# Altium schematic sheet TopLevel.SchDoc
size A4
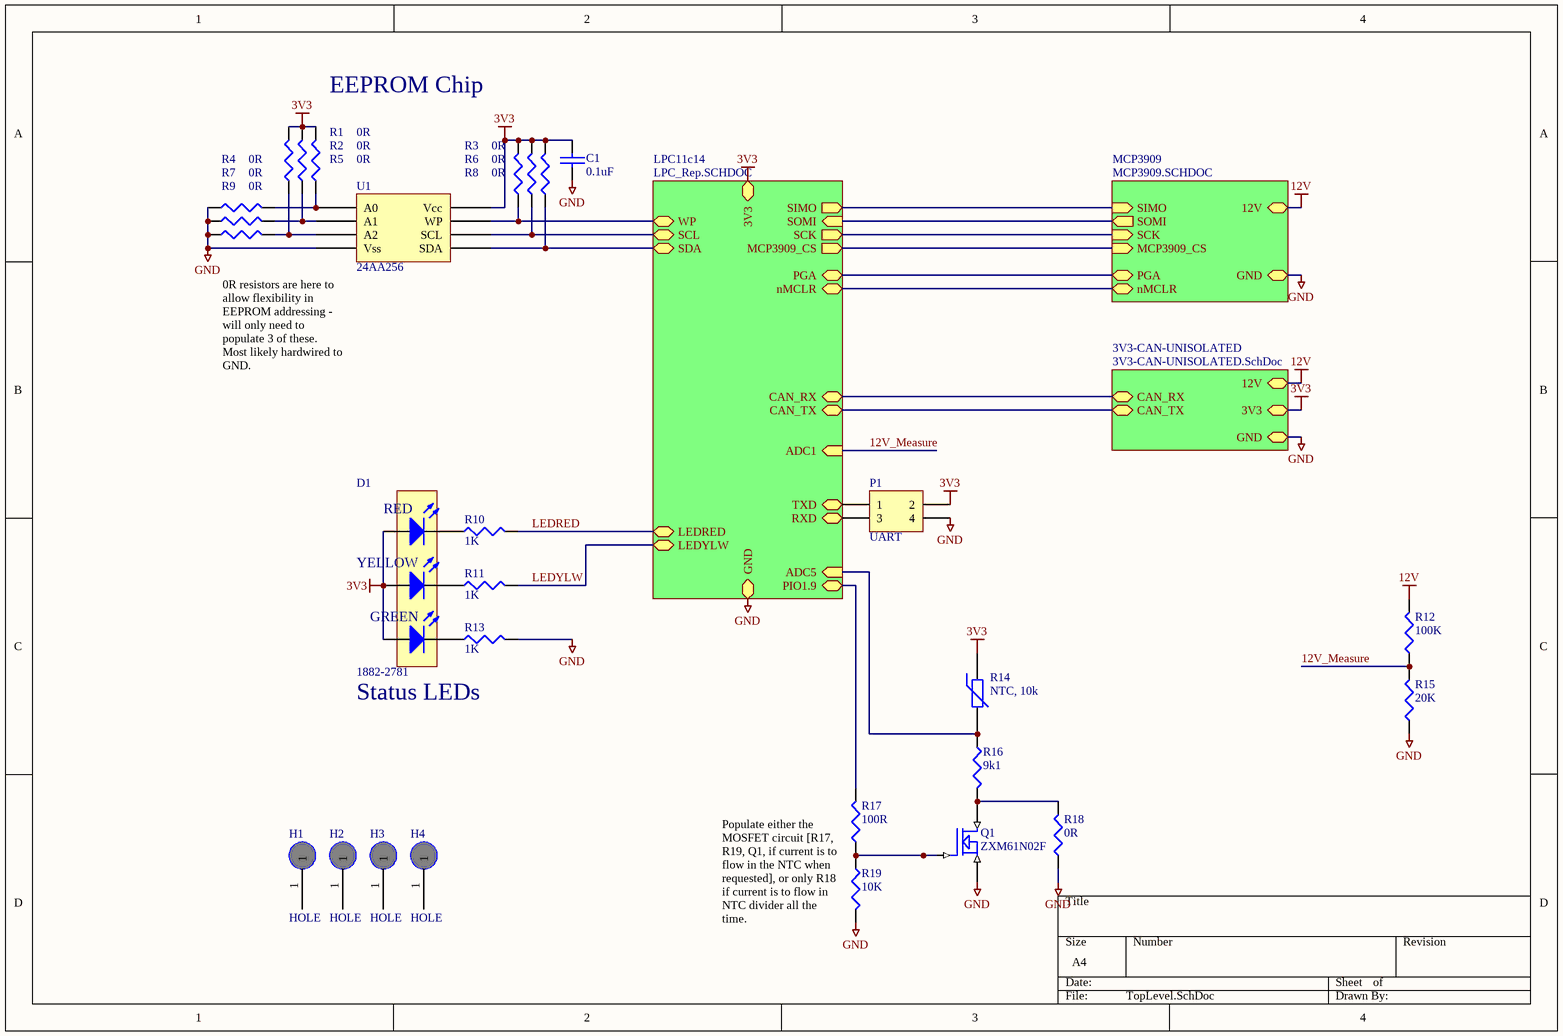
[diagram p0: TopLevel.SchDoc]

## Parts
C1  0.1uF  [0805]
D1  1882-2781  [LED_TRILEVEL]
H1  HOLE  [M2.5]
H2  HOLE  [M2.5]
H3  HOLE  [M2.5]
H4  HOLE  [M2.5]
P1  UART  [HDR2X2]
Q1  ZXM61N02F  [SOT23-3]
R1  0R  [0603]
R2  0R  [0603]
R3  0R  [0603]
R4  0R  [0603]
R5  0R  [0603]
R6  0R  [0603]
R7  0R  [0603]
R8  0R  [0603]
R9  0R  [0603]
R10  1K  [0603]
R11  1K  [0603]
R12  100K  [1206]
R13  1K  [0603]
R14  NTC, 10k  [NTC_EPCOS]
R15  20K  [1206]
R16  9k1  [0603]
R17  100R  [0603]
R18  0R  [0603]
R19  10K  [0603]
U1  24AA256  [DIP8]

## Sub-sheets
3V3-CAN-UNISOLATED = 3V3-CAN-UNISOLATED.SchDoc: CAN_RX, CAN_TX, GND, 12V, 3V3
LPC11c14 = LPC_Rep.SCHDOC: SIMO (out), SOMI (in), SCK (out), MCP3909_CS (out), PGA, nMCLR, CAN_RX, CAN_TX, 3V3, GND, SCL, SDA, WP, LEDRED, LEDYLW, ADC5 (in), PIO1.9, ADC1 (in), TXD, RXD
MCP3909 = MCP3909.SCHDOC: SIMO (in), SOMI (out), SCK (in), MCP3909_CS (in), PGA, nMCLR, 12V, GND

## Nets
3V3: C1.1 D1.4(A) D1.5(A) D1.6(A) P1.2 R1.2 R2.2 R3.2 R5.2 R6.2 R8.2 R14.1 U1.8(Vcc) ; sheet LPC11c14/3V3, sheet 3V3-CAN-UNISOLATED/3V3
12V: R12.2 ; sheet MCP3909/12V, sheet 3V3-CAN-UNISOLATED/12V
GND: C1.2 P1.4 Q1.2(S) R4.1 R7.1 R9.1 R13.2 R15.1 R18.1 R19.2 U1.4(Vss) ; sheet LPC11c14/GND, sheet MCP3909/GND, sheet 3V3-CAN-UNISOLATED/GND
12V_Measure: R12.1 R15.2 ; sheet LPC11c14/ADC1
LEDRED: R10.2 ; sheet LPC11c14/LEDRED
LEDYLW: R11.2 ; sheet LPC11c14/LEDYLW
NetD1_1: D1.1(K) R13.1
NetD1_2: D1.2(K) R11.1
NetD1_3: D1.3(K) R10.1
NetP1_1: P1.1 ; sheet LPC11c14/TXD
NetP1_3: P1.3 ; sheet LPC11c14/RXD
NetQ1_1: Q1.1(G) R17.1 R19.1
NetQ1_3: Q1.3(D) R16.2 R18.2
NetR1_1: R1.1 R4.2 U1.1(A0)
NetR2_1: R2.1 R7.2 U1.2(A1)
NetR3_1: R3.1 U1.5(SDA) ; sheet LPC11c14/SDA
NetR5_1: R5.1 R9.2 U1.3(A2)
NetR6_1: R6.1 U1.6(SCL) ; sheet LPC11c14/SCL
NetR8_1: R8.1 U1.7(WP) ; sheet LPC11c14/WP
NetR14_2: R14.2 R16.1 ; sheet LPC11c14/ADC5
NetR17_2: R17.2 ; sheet LPC11c14/PIO1.9
(unnamed): sheet LPC11c14/SIMO, sheet MCP3909/SIMO
(unnamed): sheet LPC11c14/SOMI, sheet MCP3909/SOMI  [a separate net that carries the same name]
(unnamed): sheet LPC11c14/SCK, sheet MCP3909/SCK  [a separate net that carries the same name]
(unnamed): sheet LPC11c14/MCP3909_CS, sheet MCP3909/MCP3909_CS  [a separate net that carries the same name]
(unnamed): sheet LPC11c14/PGA, sheet MCP3909/PGA  [a separate net that carries the same name]
(unnamed): sheet LPC11c14/nMCLR, sheet MCP3909/nMCLR  [a separate net that carries the same name]
(unnamed): sheet LPC11c14/CAN_RX, sheet 3V3-CAN-UNISOLATED/CAN_RX  [a separate net that carries the same name]
(unnamed): sheet LPC11c14/CAN_TX, sheet 3V3-CAN-UNISOLATED/CAN_TX  [a separate net that carries the same name]

Not connected (* = marked no-connect by the designer): H1 1; H2 1; H3 1; H4 1

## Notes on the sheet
- EEPROM Chip
- 0R resistors are here to allow flexibility in EEPROM addressing - will only need to populate 3 of these. Most likely hardwired to GND.
- Status LEDs
- Populate either the MOSFET circuit [R17, R19, Q1, if current is to flow in the NTC when requested], or only R18 if current is to flow in NTC divider all the time.

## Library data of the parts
C1 = CAP: Capacitor; Order#: ??
D1 = LED-TRILEVEL: Three level LED
P1 = Header 2X2: Header, 2-Pin, Dual row
Q1 = ZXM61N02F: 1.7A, 20V N-Channel Enhancement mode FET; Order#: 9525270
R1-R9 = RES1: Resistor; Order#: 933-1697
R10 R11 R13 = RES1: Resistor; Order#: 9331697
R12 R15 = RES1: Resistor
R14 = Res Varistor: Varistor (Voltage-Sensitive Resistor); EPCOS: B57540G0103F00
R16 = RES1: Resistor; Order#: 9330380
R17-R19 = RES1: Resistor; Order#: 9233253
